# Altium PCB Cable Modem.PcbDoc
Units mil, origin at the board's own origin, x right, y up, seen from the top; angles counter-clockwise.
Board outline 3282 x 2679 mil, 2 copper layers (Top Layer, Bottom Layer); 40 components, 37 nets, 171 pads, 23 vias.
Unrouted connection lines stored in the file: 3.
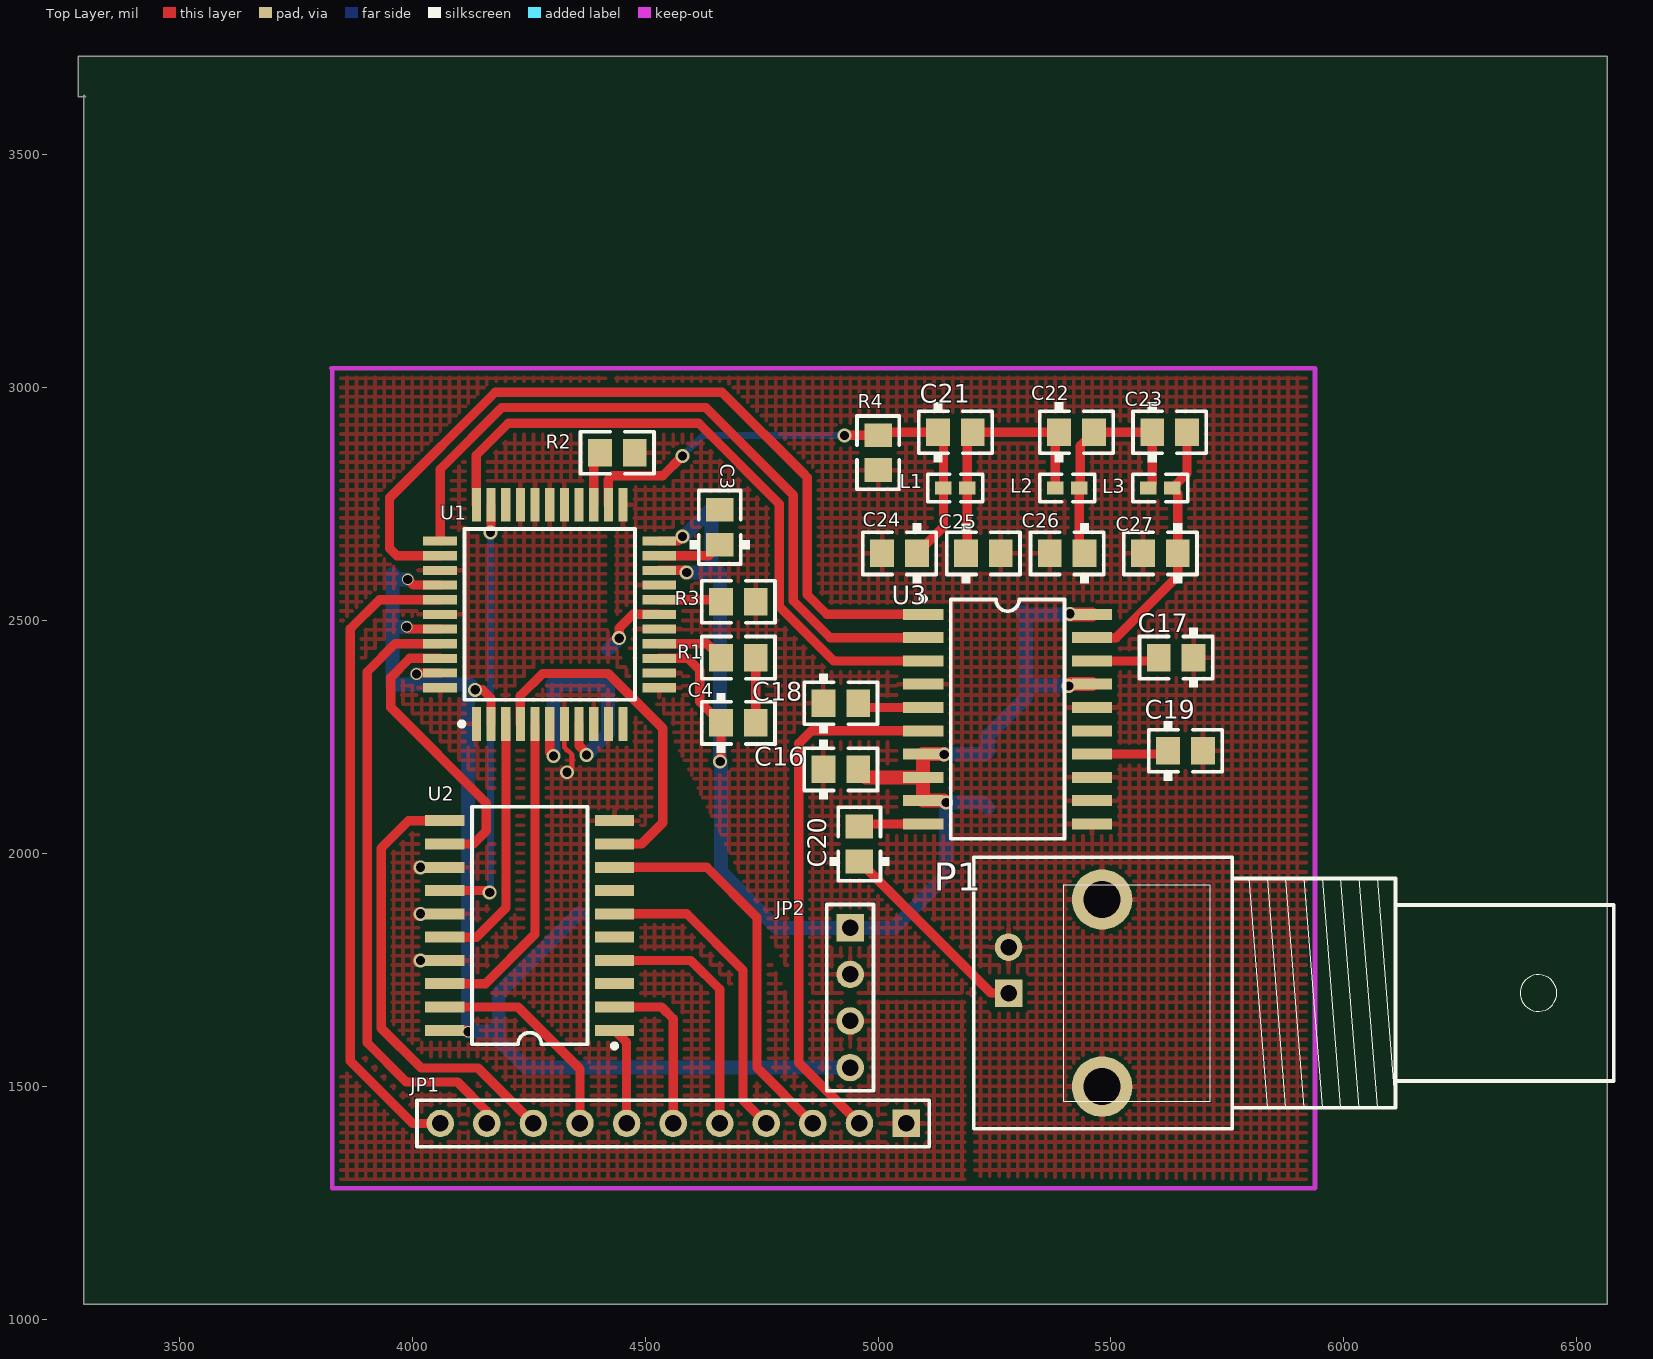
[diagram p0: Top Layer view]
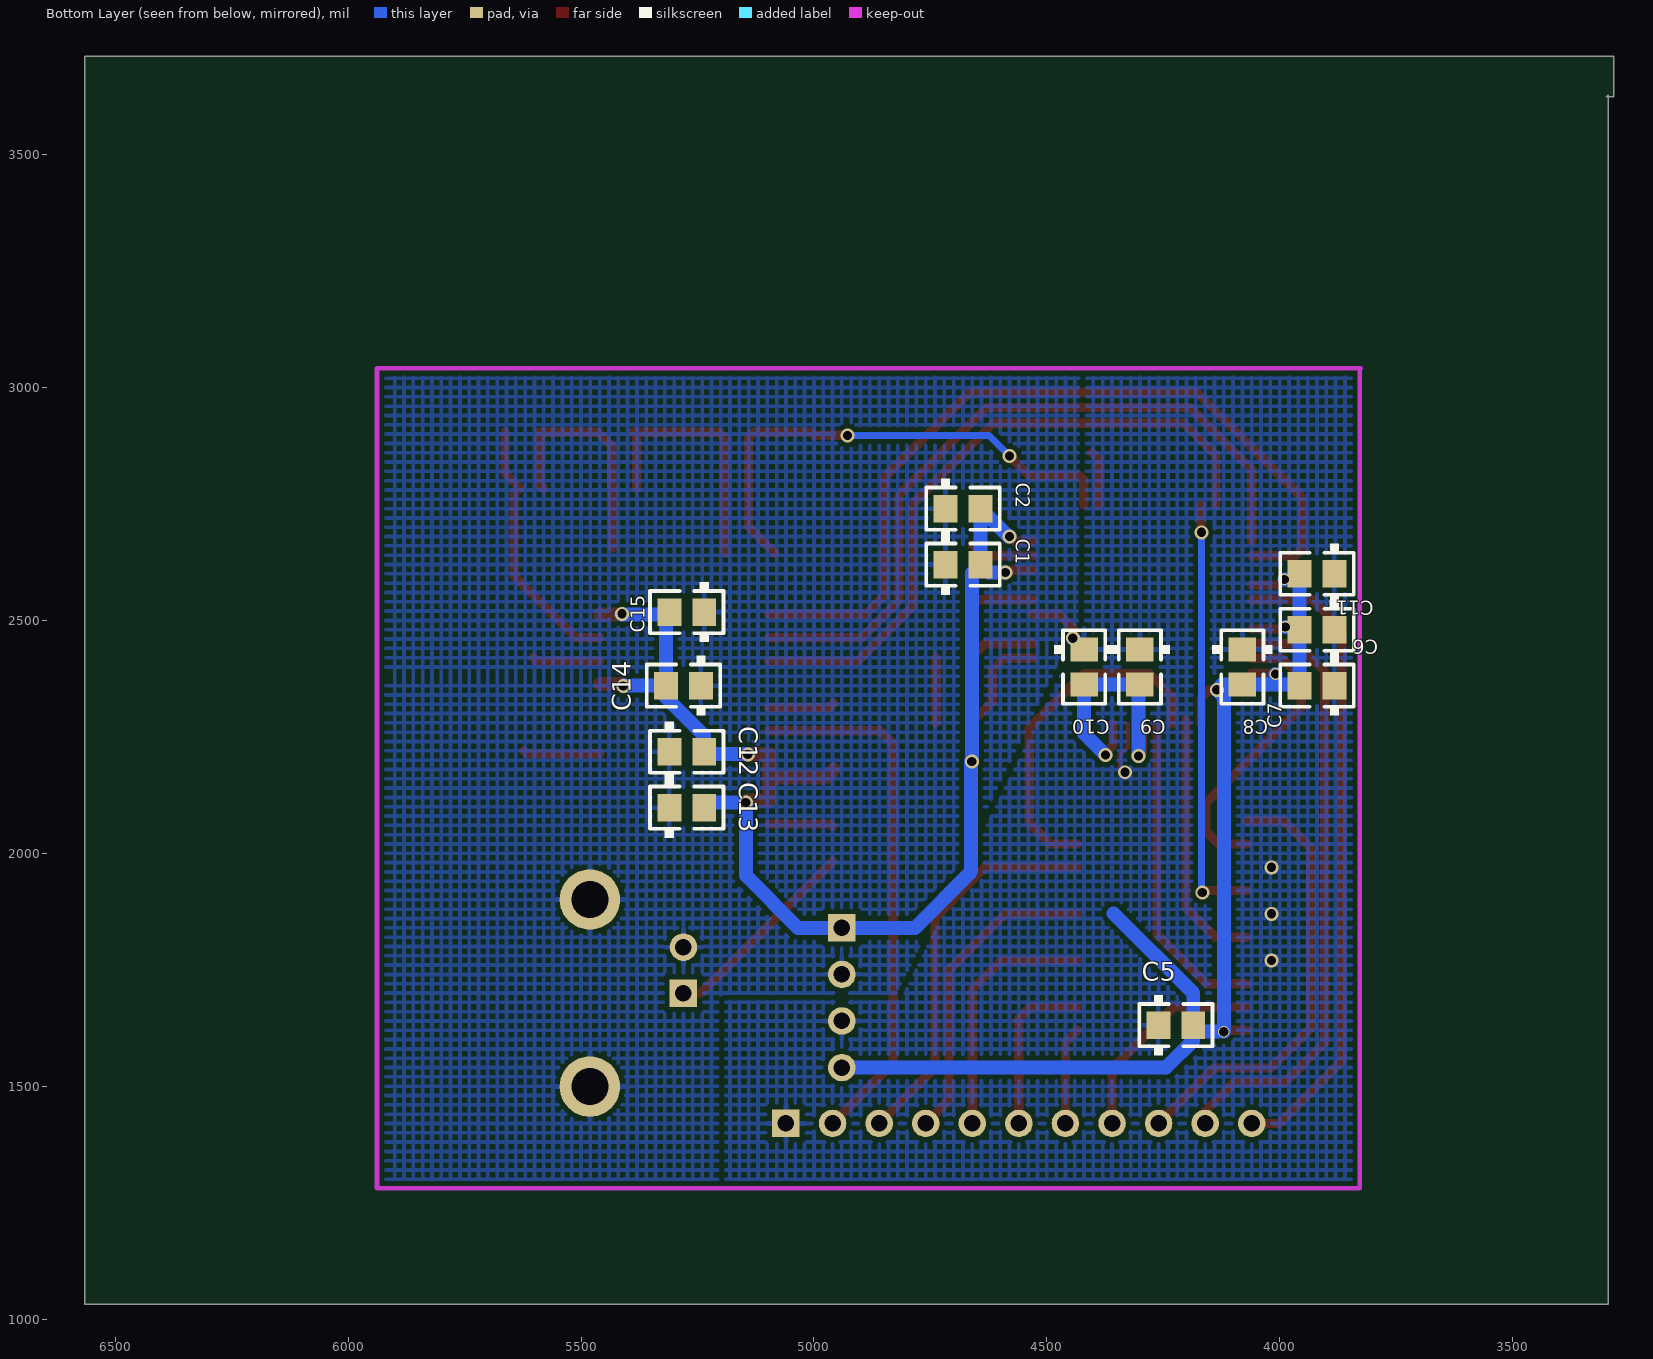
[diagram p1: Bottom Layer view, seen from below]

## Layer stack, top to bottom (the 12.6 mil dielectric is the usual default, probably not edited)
Top Layer: signal copper 1.4
Dielectric: dielectric 12.6, FR-4, Dk 4.8
Bottom Layer: signal copper 1.4

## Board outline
3295,3628 3295,1032 6565,1032 6565,3711 3283,3711 3283,3624 3299,3624

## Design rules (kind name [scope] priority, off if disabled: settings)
Clearance [All] p1: gap=10
ComponentClearance [All] p1: gap=10 collisioncheckmode=0
PolygonConnect [All] p1: connectstyle=Relief reliefconductorwidth=10 reliefentries=4 polygonreliefangle="90 Angle"
RoutingLayers [All] p1: top layer=Horizontal bottom layer=Vertical
RoutingVias [All] p1: holewidth=28 width=50 viastyle="Through Hole" minholewidth=28 minwidth=50 maxholewidth=28 maxwidth=50
SolderMaskExpansion [All] p1: expansion=4
TestPointUsage [All] p1: valid=0 allowmultiple=FALSE
Testpoint [All] p1: side=15 testpointundercomponent=TRUE minsize=40 maxsize=100 preferedsize=60 minholesize=0 maxholesize=40 preferedholesize=32 testpointgrid=1 style=1023 order=-539222988
Width Width_5 [InNet('DUT +V')] p1: maxlimit=50 minlimit=10 preferedwidth=30 toplayer_prefwidth=20 minimp=50.000000 maximp=50.000000 favimp=50.000000
Width Width_4 [InNet('+5V')] p2: maxlimit=50 minlimit=10 preferedwidth=30 toplayer_prefwidth=20 minimp=50.000000 maximp=50.000000 favimp=50.000000
Width Width_3 [InNet('AGND')] p3: maxlimit=50 minlimit=10 preferedwidth=30
Width Width_2 [InNet('SGND')] p4: maxlimit=50 minlimit=10 preferedwidth=30 toplayer_prefwidth=10 minimp=50.000000 maximp=50.000000 favimp=50.000000
Width [All] p5: maxlimit=30 minlimit=10 preferedwidth=15 toplayer_prefwidth=20 minimp=50.000000 maximp=50.000000 favimp=50.000000
16 further rules are at their usual default settings.

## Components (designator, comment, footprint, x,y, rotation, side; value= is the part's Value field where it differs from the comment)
C1 "100pF" CC2012-0805 4680,2620 r180 bottom
C2 "100pF" CC2012-0805 4680,2740 r180 bottom
C3 "100pF" CC2012-0805 4660,2700 r90 top
C4 "10pF" CC2012-0805 4700,2280 r0 top
C5 "100pF" CC2012-0805 4223,1631 r180 bottom
C6 "100pF" CC2012-0805 3920,2480 r0 bottom
C7 "100pF" CC2012-0805 3920,2360 r0 bottom
C8 "100pF" CC2012-0805 4080,2400 r270 bottom
C9 "100pF" CC2012-0805 4300,2400 r270 bottom
C10 "100pF" CC2012-0805 4420,2400 r270 bottom
C11 "100pF" CC2012-0805 3920,2600 r0 bottom
C12 "100pF" CC2012-0805 5273,2218 r180 bottom
C13 "100pF" CC2012-0805 5273,2098 r180 bottom
C14 "100pF" CC2012-0805 5280,2360 r0 bottom
C15 "100pF" CC2012-0805 5273,2518 r0 bottom
C16 "100pF" CC2012-0805 4920,2180 r0 top
C17 "100pF" CC2012-0805 5640,2420 r180 top
C18 "100pF" CC2012-0805 4920,2322 r0 top
C19 "100pF" CC2012-0805 5660,2220 r0 top
C20 "100pF" CC2012-0805 4960,2020 r90 top
C21 "7pF" CC2012-0805 5166,2904 r0 top
C22 "33pF" CC2012-0805 5426,2904 r0 top
C23 "22pF" CC2012-0805 5626,2904 r0 top
C24 "68pF" CC2012-0805 5046,2644 r180 top
C25 "100pF" CC2012-0805 5226,2644 r0 top
C26 "82pF" CC2012-0805 5406,2644 r180 top
C27 "56pF" CC2012-0805 5606,2644 r180 top
JP1 "Header 11" HDR1X11 5060,1420 r180 top
JP2 "Header 4" HDR1X4 4940,1840 r270 top
L1 "120nH" C1005-0402 5166,2784 r180 top
L2 "100nH" C1005-0402 5406,2784 r180 top
L3 "100nH" C1005-0402 5606,2784 r180 top
P1 "BNC" "BNC_RA CON" 5280,1700 r180 top
R1 "1.3K" R2012-0805 4700,2420 r0 top
R2 "25" R2012-0805 4440,2860 r0 top
R3 "3.9K" R2012-0805 4700,2540 r0 top
R4 "50" R2012-0805 5000,2860 r90 top
U1 "AD9853" QFP10X10-G44/N 4295,2513 r90 top
U2 "SN74AS244ADW" SO-G20/G7.1 4252,1845 r90 top
U3 "AD8320" SO-G20 5278,2288 r270 top

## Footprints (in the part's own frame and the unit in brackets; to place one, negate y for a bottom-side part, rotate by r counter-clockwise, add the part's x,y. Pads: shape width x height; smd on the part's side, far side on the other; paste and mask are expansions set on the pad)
"BNC_RA CON" [mm]
  rect 1.5x1.5 hole 0.9: 1(0,0)
  round 3.3 hole 2: 2(-5.1,5.1) 2(-5.1,-5.1)
  round 1.5 hole 0.9: 2(0,-2.5)
  silkscreen extent -33,-7.4 1.9,7.4
C1005-0402 [mm]
  rect 0.9x0.7 smd: 1(-0.65,0) 2(0.65,0)
  silkscreen extent -1.5,-0.75 1.5,0.75
CC2012-0805 [mm]
  rect 1.3x1.5 smd: 1(-0.95,0) 2(0.95,0)
  silkscreen extent -2,-1.65 2,1.64
HDR1X4 [mm]
  rect 1.5x1.5 hole 0.9: 1(0,0)
  round 1.5 hole 0.9: 2(2.54,0) 3(5.08,0) 4(7.62,0)
  silkscreen extent -1.27,-1.27 8.89,1.27
HDR1X11 [mm]
  rect 1.5x1.5 hole 0.9: 1(0,0)
  round 1.5 hole 0.9: 2(2.54,0) 3(5.08,0) 4(7.62,0) 5(10.16,0) 6(12.7,0) 7(15.24,0) 8(17.78,0) 9(20.32,0) 10(22.86,0) 11(25.4,0)
  silkscreen extent -1.27,-1.27 26.67,1.27
QFP10X10-G44/N [mm]
  rect 1.85x0.5 smd: 1(-5.975,4) 2(-5.975,3.2) 3(-5.975,2.4) 4(-5.975,1.6) 5(-5.975,0.8) 6(-5.975,0) 7(-5.975,-0.8) 8(-5.975,-1.6) 9(-5.975,-2.4) 10(-5.975,-3.2) 11(-5.975,-4) 23(5.975,-4) 24(5.975,-3.2) 25(5.975,-2.4) 26(5.975,-1.6) 27(5.975,-0.8) 28(5.975,0) 29(5.975,0.8) 30(5.975,1.6) 31(5.975,2.4) 32(5.975,3.2) 33(5.975,4)
  rect 0.5x1.85 smd: 12(-4,-5.975) 13(-3.2,-5.975) 14(-2.4,-5.975) 15(-1.6,-5.975) 16(-0.8,-5.975) 17(0,-5.975) 18(0.8,-5.975) 19(1.6,-5.975) 20(2.4,-5.975) 21(3.2,-5.975) 22(4,-5.975) 34(4,5.975) 35(3.2,5.975) 36(2.4,5.975) 37(1.6,5.975) 38(0.8,5.975) 39(0,5.975) 40(-0.8,5.975) 41(-1.6,5.975) 42(-2.4,5.975) 43(-3.2,5.975) 44(-4,5.975)
  silkscreen extent -6.1,-4.65 4.65,4.92
R2012-0805 [mm]
  rect 1.3x1.5 smd: 1(-0.95,0) 2(0.95,0)
  silkscreen extent -2,-1.15 2,1.15
SO-G20 [mm]
  rect 0.6x2.2 smd: 1(-5.715,-4.6) 2(-4.445,-4.6) 3(-3.175,-4.6) 4(-1.905,-4.6) 5(-0.635,-4.6) 6(0.635,-4.6) 7(1.905,-4.6) 8(3.175,-4.6) 9(4.445,-4.6) 10(5.715,-4.6) 11(5.715,4.6) 12(4.445,4.6) 13(3.175,4.6) 14(1.905,4.6) 15(0.635,4.6) 16(-0.635,4.6) 17(-1.905,4.6) 18(-3.175,4.6) 19(-4.445,4.6) 20(-5.715,4.6)
  silkscreen extent -6.69,-4.72 6.53,3.1
SO-G20/G7.1 [mm]
  rect 0.6x2.15 smd: 1(-5.715,-4.625) 2(-4.445,-4.625) 3(-3.175,-4.625) 4(-1.905,-4.625) 5(-0.635,-4.625) 6(0.635,-4.625) 7(1.905,-4.625) 8(3.175,-4.625) 9(4.445,-4.625) 10(5.715,-4.625) 11(5.715,4.625) 12(4.445,4.625) 13(3.175,4.625) 14(1.905,4.625) 15(0.635,4.625) 16(-0.635,4.625) 17(-1.905,4.625) 18(-3.175,4.625) 19(-4.445,4.625) 20(-5.715,4.625)
  silkscreen extent -6.69,-4.75 6.47,3.15

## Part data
C1 C2 C3 C4 C5 C6 C7 C8 C9 C10 C11 C12 C13 C14 C15 C16 C17 C18 C19 C20: library part Cap, "Capacitor"
C21 C22 C23 C24 C25 C26 C27: library part "Cap Semi", "Capacitor (Semiconductor SIM Model)"
JP1: "Header, 11-Pin"
JP2: "Header, 4-Pin"
L1 L2 L3: library part Inductor, "Inductor"
P1: "BNC Elbow Connector"
R1 R2 R3 R4: library part Res1, "Resistor"
U1: "Programmable Digital QPSK/16-QAM Modulator"
U2: "Octal Buffer/Driver with 3-State Outputs"

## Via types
v1: diameter 30, hole 20, Top Layer to Bottom Layer, 19 vias
v2: diameter 25, hole 20, Top Layer to Bottom Layer, 4 vias

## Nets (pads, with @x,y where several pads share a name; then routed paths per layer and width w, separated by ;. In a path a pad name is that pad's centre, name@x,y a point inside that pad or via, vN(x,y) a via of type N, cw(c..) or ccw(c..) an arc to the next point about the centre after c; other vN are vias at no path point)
+5V: C1.2 C2.2 C3.2 C4.1 C12.2 C13.2 C14.2 C15.2 C16.2 JP2.1 U1.14 U1.20 U1.22 U3.7 U3.8 U3.9 U3.17 U3.20 | length 3260.1
  Top Layer w20: U1.14 4591.49,2418.51 4617.01,2392.99 4617.01,2325.59 C4.1 4662.6,2198.6 v1(4661,2197) ; U1.20 4584.51,2607.49 v1(4589,2603) ; U1.22 4570.48,2670.48 v1(4580,2680)
  Top Layer w30: C16.2 4974.4,2163 U3.8 ; v1(5142,2212) 5141,2213 U3.7 U3.9 5142,2113 v1(5146,2109) ; v1(5409,2359) 5413,2363 U3.17 ; v1(5412,2514) 5413,2513 U3.20
  Bottom Layer w30: v1(4580,2680) 4582.6,2680 C2.2 C1.2 ; v1(4589,2603) 4625.6,2603 C1.2 ; v1(4661,2197) 4661,2601.6 C1.2 ; v1@4662.6,2198.6 4662.6,1960.4 4783,1840 5034,1840 5146,1952 v1(5146,2109) 5224.6,2109 C13.2 ; v1@5141,2213 5230.6,2213 C12.2 5235.6,2252.6 5317.4,2334.4 5317.4,2511 C15.2 ; C15.2@5315.4,2513 v1@5413,2513 ; C14.2 5408,2360 v1(5409,2359)
A5: JP1.9 U2.11 | length 959.3
  Top Layer w20: U2.11 3992,2070 3933,2011 3933,1625 4019,1539 4141,1539 JP1.9
A6: 
AGND: C1.1 C2.1 C12.1 C13.1 C14.1 C15.1 C16.1 C17.1 C18.1 C19.2 C24.2 C25.2 C26.2 C27.2 JP2.2 P1.2 R2.2 R3.2 R4.1 U1.12 U1.13 U1.16 U1.19 U1.23 U3.4 U3.11 U3.12 U3.13 U3.16
"DUT +V": C5.2 C6.2 C7.2 C8.2 C9.2 C10.2 C11.2 JP2.4 U1.2 U1.6 U1.8 U1.37 U1.40 U1.43 U2.20 | length 3385.6
  Top Layer w20: v2(3988,2486) 3992.5,2481.5 U1.40 ; v2(3990,2588) 4002.01,2575.99 U1.37 ; v2(4009,2385) 4011.02,2387.02 U1.43 ; U2.20 4117,1620 v2(4120,1617) ; v1(4135,2351) 4151,2351 4169.02,2332.98 U1.2 ; U1.6 4295,2217 v1(4303,2209) ; U1.8 4357.99,2231.51 v1@4374,2215.5
  Bottom Layer w30: C6.2 3963.4,2486 v2(3988,2486) ; v2(3990,2588) 3969.4,2588 C11.2 C7.2 3960,2362.6 4123.4,2362.6 v1(4135,2351) 4120,2336 v2(4120,1617) 4171.6,1617 C5.2 ; v2(4009,2385) 4009,2364.6 4011,2362.6 ; v1(4303,2209) 4303,2359.6 C9.2 C10.2 4420,2257 v1(4374,2211) ; 4357,1871 4185.6,1699.6 4185.6,1598.4 4244,1540 JP2.4
NetC3_1: C3.1 U1.21 | length 139.5
  Top Layer w20: U1.21 4636.39,2638.99 C3.1
NetC4_2: C4.2 R1.2 | length 140
  Top Layer w20: C4.2 R1.2
NetC17_2: C17.2 U3.18 | length 146.4
  Top Layer w20: U3.18 5595.6,2413 C17.2
NetC18_2: C18.2 U3.5 | length 143.2
  Top Layer w20: C18.2 4966.4,2313 U3.5
NetC19_1: C19.1 U3.14 | length 166.4
  Top Layer w20: U3.14 5615.6,2213 C19.1
NetC20_1: C20.1 P1.1 | length 437.1
  Top Layer w20: C20.1 5242.6,1700 P1.1
NetC20_2: C20.2 U3.10 | length 139.2
  Top Layer w20: C20.2 4965.6,2063 U3.10
NetC21_1: C21.1 C24.1 L1.2 R4.2 U1.24 | length 1082.6
  Top Layer w20: U1.24 4420.98,2801.99 4429.47,2810.47 4537.47,2810.47 v1(4580.02,2853.01) ; v1@4937.4,2897.4 R4.2 5006.6,2904 C21.1 5140.41,2892.19 L1.2 5140.41,2701.01 C24.1
  Bottom Layer w15: v1(4580.02,2853.01) 4624,2897 v1(4928,2897)
NetC21_2: C21.2 C22.1 C25.1 L1.1 L2.2 | length 574.7
  Top Layer w20: C25.1 5191.59,2646.99 5191.59,2892.19 C21.2 C22.1 5380.41,2895.81 L2.2
NetC22_2: C22.2 C23.1 C26.1 L2.1 L3.2 | length 506.3
  Top Layer w20: C26.1@5431.59,2655.81 L2.1 ; L2.1@5434.19,2786.6 5434.19,2874.79 C22.2 C23.1 5588.6,2792.19 L3.2
NetC23_2: C23.2 C27.1 L3.1 U3.19 | length 565.8
  Top Layer w20: U3.19 5511,2463 5643.4,2595.4 5643.4,2772.19 L3.1 5663.4,2815.81 C23.2
NetJP1_3: JP1.3 U2.8 | length 842.4
  Top Layer w20: U2.8 4632,1970 4740,1862 4740,1540 JP1.3
NetJP1_4: JP1.4 U2.6 | length 675.7
  Top Layer w20: U2.6 4589,1870 4710,1749 4710,1470 JP1.4
NetJP1_5: JP1.5 U2.4 | length 539.6
  Top Layer w20: U2.4 4598,1770 4660,1708 JP1.5
NetJP1_6: JP1.6 U2.2 | length 361.3
  Top Layer w20: U2.2 4535,1670 4560,1645 JP1.6
NetJP1_10: JP1.10 U1.41 | length 1322.5
  Top Layer w20: U1.41 3963.01,2450.01 3903,2390 3903,1593 3987,1509 4097,1509 4160,1446 JP1.10
NetJP1_11: JP1.11 U1.38 | length 1395.2
  Top Layer w20: U1.38 3929.5,2544.5 3867,2482 3867,1554 4001,1420 JP1.11
NetR1_1: R1.1 U1.15 | length 144.8
  Top Layer w20: U1.15 4632.59,2450.01 R1.1
NetR2_1: R2.1 U1.25 | length 117.2
  Top Layer w20: U1.25 4389.49,2846.89 R2.1
NetR3_1: R3.1 U1.18 | length 134.2
  Top Layer w20: U1.18 4658.1,2544.5 R3.1
NetU1_3: U1.3 U2.16 | length 561.2
  Top Layer w20: U2.16 4138,1820 4201,1883 U1.3@4201,2287
NetU1_4: U1.4 U2.9 | length 760
  Top Layer w20: U1.4 4232.01,2338.01 4280,2386 4420,2386 4538,2268 4538,2066 4492,2020 U2.9
NetU1_5: U1.5 U2.18 | length 689
  Top Layer w20: U2.18 4157,1720 4263.5,1826.5 U1.5
NetU1_32: U1.32 U2.14 | length 930.4
  Top Layer w20: U2.14 4162,1920 v1(4166,1916) ; v1@4169.02,2690.02 U1.32
  Bottom Layer w15: v1@4167,1915 4168,1916 v1(4168,2689)
NetU1_33: U1.33 U3.3 | length 1434.1
  Top Layer w20: U1.33 4137.52,2854.52 4206,2923 4615,2923 4788,2750 4788,2530 4905,2413 U3.3
NetU1_34: U1.34 U3.2 | length 1583.5
  Top Layer w20: U1.34 4059.76,2824.76 4192,2957 4630,2957 4818,2769 4818,2542.43 4897.43,2463 U3.2
NetU1_35: U1.35 U3.1 | length 1801.5
  Top Layer w20: U1.35 3967.01,2638.99 3951,2655 3951,2763 4178,2990 4665,2990 4843,2812 ; 4848,2807 4848,2554.85 4889.85,2513 U3.1
NetU1_42: U1.42 U2.12 | length 638.1
  Top Layer w20: U1.42 3994.51,2418.51 3954,2378 3954,2313 4159,2108 4159,2048 4131,2020 U2.12
OE1: JP1.7 U2.1 | length 210.7
  Top Layer w20: U2.1 4460,1594.09 JP1.7
OE2: JP1.8 U2.19 | length 462.2
  Top Layer w20: U2.19 4227,1670 4360,1537 JP1.8
PD: JP1.2 U3.6 | length 1147.9
  Top Layer w20: JP1.2 4830,1550 4830,2236 4857,2263 U3.6
SGND: C5.1 C6.1 C7.1 C8.1 C9.1 C10.1 C11.1 JP1.1 JP2.3 U1.1 U1.7 U1.9 U1.10 U1.17 U1.27 U1.28 U1.29 U1.30 U1.36 U1.39 U1.44 U2.10 U2.13 U2.15 U2.17 | length 269.4
  Top Layer w10: U1.7 4326.5,2227.65 4343,2211.15 4343,2185 v1(4332,2174)
  Top Layer w20: v1(4444,2462) 4444,2483 4474,2513 U1.17
  Bottom Layer w30: C10.1 4444,2461.4 v1(4444,2462)
  other v1: 4017.59,1770 4017.59,1870 4017.59,1970
pads on no net: U1.11 U1.26 U1.31 U2.3 U2.5 U2.7 U3.15

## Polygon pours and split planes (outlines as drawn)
SGND on Top Layer (hatched 90Degree grid 20 track 8, remove dead copper): 5179,1682 4810,1682 4415,2486 4415,3039 3830,3039 3830,1284 5186,1284 5186,1683
AGND on Top Layer (hatched 90Degree grid 20 track 8, remove dead copper): 4437,3019 4437,2499 4830,1701 5204,1690 5208,1307 5928,1299 5931,3042 4435,3034 4435,3024
SGND on Bottom Layer (hatched 90Degree grid 20 track 8, remove dead copper): 5189,1294 5189,1682 4813,1682 4417,2490 4414,3037 3838,3034 3838,1281 5192,1281 5192,1299
AGND on Bottom Layer (hatched 90Degree grid 20 track 8, remove dead copper): 4424,3034 4424,2494 4826,1698 5207,1687 5203,1283 5938,1281 5939,3037 4421,3029

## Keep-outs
Keep-Out Layer:
  lines w10: 3826,3041 5938,3041 5938,2991 5938,1281 3828,1281 3828,3007 3828,3039 3826,3041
